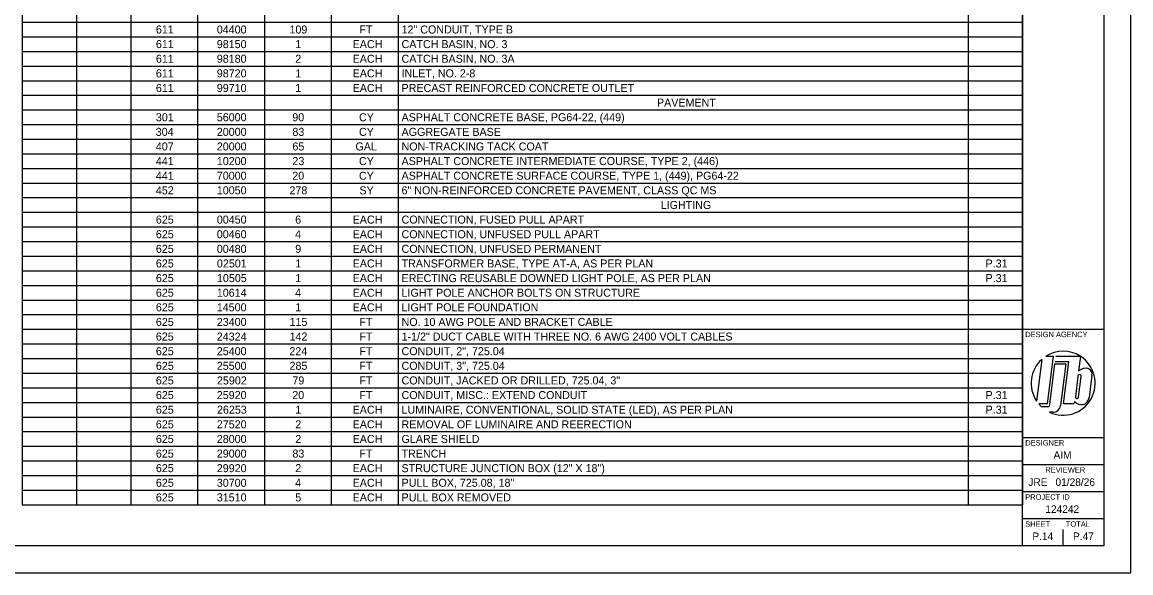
# Model space of a CAD drawing. Extents: x 0 to 34, y 0 to 22.
# Drawn here: x 13.53 to 34, y 0 to 10.16 of the extents above; entities that cross this region are included whole.
import ezdxf

# ---------------------------------------------------------------- set-up
doc = ezdxf.new("R2010")
doc.units = 0
for name, color, linetype in [('Default', 7, 'Continuous'), ('SH_Border', 7, 'Continuous'), ('SH_Cut_Line', 7, 'Continuous'), ('SH_Data', 7, 'Continuous')]:
    doc.layers.add(name, color=color, linetype=linetype)

msp = doc.modelspace()

# ---------------------------------------------------------------- linework, layer by layer
at = {"layer": 'Default'}
for p, q in [((13.53, 10.434), (13.53, 10.164)), ((14.533, 10.434), (14.533, 10.164)), ((15.535, 10.434), (15.535, 10.164)), ((16.769, 10.434), (16.769, 10.164)), ((18.003, 10.434), (18.003, 10.164)), ((19.237, 10.434), (19.237, 10.164)), ((20.471, 10.434), (20.471, 10.164)), ((30.997, 10.434), (30.997, 10.164)), ((32, 10.434), (32, 10.164)), ((13.53, 10.164), (15.535, 10.164)), ((13.53, 10.164), (13.53, 9.354)), ((14.533, 10.164), (14.533, 9.354)), ((15.535, 10.164), (32, 10.164)), ((15.535, 10.164), (15.535, 9.354)), ((16.769, 10.164), (16.769, 9.354)), ((18.003, 10.164), (18.003, 9.354)), ((19.237, 10.164), (19.237, 9.354)), ((20.471, 10.164), (20.471, 9.354)), ((30.997, 10.164), (30.997, 9.354)), ((32, 10.164), (32, 9.354)), ((13.53, 9.894), (15.535, 9.894)), ((15.535, 9.894), (32, 9.894)), ((13.53, 9.624), (15.535, 9.624)), ((15.535, 9.624), (32, 9.624)), ((13.53, 9.354), (15.535, 9.354)), ((13.53, 9.354), (13.53, 8.814)), ((14.533, 9.354), (14.533, 8.814)), ((15.535, 9.354), (32, 9.354)), ((15.535, 9.354), (15.535, 8.814)), ((16.769, 9.354), (16.769, 8.814)), ((18.003, 9.354), (18.003, 8.814)), ((19.237, 9.354), (19.237, 8.814)), ((20.471, 9.354), (20.471, 8.814)), ((30.997, 9.354), (30.997, 8.814)), ((32, 9.354), (32, 8.814)), ((13.53, 9.084), (15.535, 9.084)), ((15.535, 9.084), (32, 9.084)), ((13.53, 8.814), (15.535, 8.814)), ((13.53, 8.814), (13.53, 8.004)), ((14.533, 8.814), (14.533, 8.004)), ((15.535, 8.814), (32, 8.814)), ((15.535, 8.814), (15.535, 8.004)), ((16.769, 8.814), (16.769, 8.004)), ((18.003, 8.814), (18.003, 8.004)), ((19.237, 8.814), (19.237, 8.004)), ((20.471, 8.814), (20.471, 8.004)), ((30.997, 8.814), (30.997, 8.004)), ((32, 8.814), (32, 8.004)), ((13.53, 8.544), (15.535, 8.544)), ((15.535, 8.544), (32, 8.544)), ((13.53, 8.274), (15.535, 8.274)), ((15.535, 8.274), (32, 8.274)), ((13.53, 8.004), (15.535, 8.004)), ((13.53, 8.004), (13.53, 7.465)), ((14.533, 8.004), (14.533, 7.465)), ((15.535, 8.004), (32, 8.004)), ((15.535, 8.004), (15.535, 7.465)), ((16.769, 8.004), (16.769, 7.465)), ((18.003, 8.004), (18.003, 7.465)), ((19.237, 8.004), (19.237, 7.465)), ((20.471, 8.004), (20.471, 7.465)), ((30.997, 8.004), (30.997, 7.465)), ((32, 8.004), (32, 7.465)), ((13.53, 7.735), (15.535, 7.735)), ((15.535, 7.735), (32, 7.735)), ((13.53, 7.465), (15.535, 7.465)), ((13.53, 7.465), (13.53, 6.655)), ((14.533, 7.465), (14.533, 6.655)), ((15.535, 7.465), (32, 7.465)), ((15.535, 7.465), (15.535, 6.655)), ((16.769, 7.465), (16.769, 6.655)), ((18.003, 7.465), (18.003, 6.655)), ((19.237, 7.465), (19.237, 6.655)), ((20.471, 7.465), (20.471, 6.655)), ((30.997, 7.465), (30.997, 6.655)), ((32, 7.465), (32, 6.655)), ((13.53, 7.195), (15.535, 7.195)), ((15.535, 7.195), (32, 7.195)), ((13.53, 6.925), (15.535, 6.925)), ((15.535, 6.925), (32, 6.925)), ((13.53, 6.655), (15.535, 6.655)), ((13.53, 6.655), (13.53, 5.575)), ((14.533, 6.655), (14.533, 5.575)), ((15.535, 6.655), (32, 6.655)), ((15.535, 6.655), (15.535, 5.575)), ((16.769, 6.655), (16.769, 5.575)), ((18.003, 6.655), (18.003, 5.575)), ((19.237, 6.655), (19.237, 5.575)), ((20.471, 6.655), (20.471, 5.575)), ((30.997, 6.655), (30.997, 5.575)), ((32, 6.655), (32, 5.575)), ((13.53, 6.385), (15.535, 6.385)), ((15.535, 6.385), (32, 6.385)), ((13.53, 6.115), (15.535, 6.115)), ((15.535, 6.115), (32, 6.115)), ((13.53, 5.845), (15.535, 5.845)), ((15.535, 5.845), (32, 5.845)), ((13.53, 5.575), (15.535, 5.575)), ((13.53, 5.575), (13.53, 5.305)), ((14.533, 5.575), (14.533, 5.305)), ((15.535, 5.575), (32, 5.575)), ((15.535, 5.575), (15.535, 5.305)), ((16.769, 5.575), (16.769, 5.305)), ((18.003, 5.575), (18.003, 5.305)), ((19.237, 5.575), (19.237, 5.305)), ((20.471, 5.575), (20.471, 5.305)), ((30.997, 5.575), (30.997, 5.305)), ((32, 5.575), (32, 5.305)), ((13.53, 5.305), (15.535, 5.305)), ((13.53, 5.305), (13.53, 4.226)), ((14.533, 5.305), (14.533, 4.226)), ((15.535, 5.305), (32, 5.305)), ((15.535, 5.305), (15.535, 4.226)), ((16.769, 5.305), (16.769, 4.226)), ((18.003, 5.305), (18.003, 4.226)), ((19.237, 5.305), (19.237, 4.226)), ((20.471, 5.305), (20.471, 4.226)), ((30.997, 5.305), (30.997, 4.226)), ((32, 5.305), (32, 4.226)), ((13.53, 5.035), (15.535, 5.035)), ((15.535, 5.035), (32, 5.035)), ((13.53, 4.765), (15.535, 4.765)), ((15.535, 4.765), (32, 4.765)), ((13.53, 4.496), (15.535, 4.496)), ((15.535, 4.496), (32, 4.496)), ((13.53, 4.226), (15.535, 4.226)), ((13.53, 4.226), (13.53, 3.956)), ((14.533, 4.226), (14.533, 3.956)), ((15.535, 4.226), (32, 4.226)), ((15.535, 4.226), (15.535, 3.956)), ((16.769, 4.226), (16.769, 3.956)), ((18.003, 4.226), (18.003, 3.956)), ((19.237, 4.226), (19.237, 3.956)), ((20.471, 4.226), (20.471, 3.956)), ((30.997, 4.226), (30.997, 3.956)), ((32, 4.226), (32, 3.956)), ((13.53, 3.956), (15.535, 3.956)), ((13.53, 3.956), (13.53, 2.876)), ((14.533, 3.956), (14.533, 2.876)), ((15.535, 3.956), (32, 3.956)), ((15.535, 3.956), (15.535, 2.876)), ((16.769, 3.956), (16.769, 2.876)), ((18.003, 3.956), (18.003, 2.876)), ((19.237, 3.956), (19.237, 2.876)), ((20.471, 3.956), (20.471, 2.876)), ((30.997, 3.956), (30.997, 2.876)), ((32, 3.956), (32, 2.876)), ((13.53, 3.686), (15.535, 3.686)), ((15.535, 3.686), (32, 3.686)), ((13.53, 3.416), (15.535, 3.416)), ((15.535, 3.416), (32, 3.416)), ((13.53, 3.146), (15.535, 3.146)), ((15.535, 3.146), (32, 3.146)), ((13.53, 2.876), (15.535, 2.876)), ((13.53, 2.876), (13.53, 2.606)), ((14.533, 2.876), (14.533, 2.606)), ((15.535, 2.876), (32, 2.876)), ((15.535, 2.876), (15.535, 2.606)), ((16.769, 2.876), (16.769, 2.606)), ((18.003, 2.876), (18.003, 2.606)), ((19.237, 2.876), (19.237, 2.606)), ((20.471, 2.876), (20.471, 2.606)), ((30.997, 2.876), (30.997, 2.606)), ((32, 2.876), (32, 2.606)), ((13.53, 2.606), (15.535, 2.606)), ((13.53, 2.606), (13.53, 1.527)), ((14.533, 2.606), (14.533, 1.527)), ((15.535, 2.606), (32, 2.606)), ((15.535, 2.606), (15.535, 1.527)), ((16.769, 2.606), (16.769, 1.527)), ((18.003, 2.606), (18.003, 1.527)), ((19.237, 2.606), (19.237, 1.527)), ((20.471, 2.606), (20.471, 1.527)), ((30.997, 2.606), (30.997, 1.527)), ((32, 2.606), (32, 1.527)), ((13.53, 2.336), (15.535, 2.336)), ((15.535, 2.336), (32, 2.336)), ((13.53, 2.066), (15.535, 2.066)), ((15.535, 2.066), (32, 2.066)), ((13.53, 1.796), (15.535, 1.796)), ((15.535, 1.796), (32, 1.796)), ((13.53, 1.527), (15.535, 1.527)), ((13.53, 1.527), (13.53, 1.257)), ((14.533, 1.527), (14.533, 1.257)), ((15.535, 1.527), (32, 1.527)), ((15.535, 1.527), (15.535, 1.257)), ((16.769, 1.527), (16.769, 1.257)), ((18.003, 1.527), (18.003, 1.257)), ((19.237, 1.527), (19.237, 1.257)), ((20.471, 1.527), (20.471, 1.257)), ((30.997, 1.527), (30.997, 1.257)), ((32, 1.527), (32, 1.257)), ((13.53, 1.257), (15.535, 1.257)), ((15.535, 1.257), (32, 1.257))]:
    msp.add_line(p, q, dxfattribs=at)
at = {"layer": 'SH_Border'}
for p, q in [((32, 0.5), (32, 21.5)), ((32, 4.5), (33.5, 4.5)), ((32, 2.5), (33.5, 2.5)), ((32, 2), (33.5, 2)), ((32, 1.5), (33.5, 1.5)), ((32, 1), (33.5, 1))]:
    msp.add_line(p, q, dxfattribs=at)
msp.add_lwpolyline([(1.5, 21.5), (33.5, 21.5), (33.5, 0.5), (1.5, 0.5)], close=True, dxfattribs=at)
at = {"layer": 'SH_Cut_Line'}
msp.add_lwpolyline([(0, 0), (34, 0), (34, 22), (0, 22)], close=True, dxfattribs=at)
at = {"layer": 'SH_Data'}
for p, q in [((32.356, 3.94), (32.259, 3.171)), ((32.432, 3.998), (32.567, 3.998)), ((32.567, 3.998), (32.456, 3.118)), ((32.856, 3.896), (32.604, 3.896)), ((32.617, 4), (33.065, 4)), ((32.758, 3.118), (32.856, 3.896)), ((33.07, 3.996), (33.035, 3.72)), ((32.504, 3.104), (32.599, 3.855)), ((32.599, 3.855), (32.801, 3.855)), ((32.801, 3.855), (32.704, 3.089)), ((32.75, 3.5), (32.75, 3.5)), ((33.024, 3.631), (32.976, 3.25)), ((33.036, 3.243), (33.084, 3.624)), ((33.283, 3.648), (33.231, 3.237)), ((32.456, 3.118), (32.299, 3.118)), ((32.947, 3.118), (32.758, 3.118)), ((32.964, 3.161), (32.947, 3.118)), ((32.347, 3.068), (32.462, 3.068)), ((32.564, 2.966), (32.498, 2.966)), ((32.375, 0.675), (32.375, 0.675)), ((32.75, 0.5), (32.75, 0.8))]:
    msp.add_line(p, q, dxfattribs=at)
for centre, radius, start, end in [((32.75, 3.5), 0.591, 131.8253, 213.7822), ((32.75, 3.5), 0.591, 57.726, 122.5688), ((32.75, 3.5), 0.591, 244.7646, 57.1575), ((33.17, 3.586), 0.19, 105.9444, 135.0487), ((33.164, 3.6), 0.175, 66.6782, 105.4185), ((33.177, 3.669), 0.108, 349.2072, 58.7163), ((33.054, 3.628), 0.0301, 352.3298, 173.2777), ((32.75, 3.5), 0.591, 220.2786, 227.0158), ((32.462, 3.109), 0.0417, 270, 352.8038), ((32.564, 3.106), 0.141, 270, 352.8038), ((33.081, 3.255), 0.151, 218.6264, 353.0883), ((33.006, 3.246), 0.0301, 172.3335, 353.274)]:
    msp.add_arc(centre, radius, start, end, dxfattribs=at)

# ---------------------------------------------------------------- texts
at = {"layer": 'Default'}
for s, height, p in [('611', 0.1478, (15.999, 9.955)), ('04400', 0.1478, (17.124, 9.955)), ('109', 0.1478, (18.466, 9.955)), ('FT', 0.1478, (19.756, 9.955)), ('12" CONDUIT, TYPE B', 0.14781, (20.535, 9.955)), ('611', 0.1478, (15.999, 9.685)), ('98150', 0.1478, (17.124, 9.685)), ('1', 0.148, (18.573, 9.685)), ('EACH', 0.1478, (19.632, 9.685)), ('CATCH BASIN, NO. 3', 0.14781, (20.535, 9.685)), ('611', 0.1478, (15.999, 9.415)), ('98180', 0.1478, (17.124, 9.415)), ('2', 0.148, (18.573, 9.415)), ('EACH', 0.1478, (19.632, 9.415)), ('CATCH BASIN, NO. 3A', 0.14781, (20.535, 9.415)), ('611', 0.1478, (15.999, 9.145)), ('98720', 0.1478, (17.124, 9.145)), ('1', 0.148, (18.573, 9.145)), ('EACH', 0.1478, (19.632, 9.145)), ('INLET, NO. 2-8', 0.14781, (20.535, 9.145)), ('611', 0.1478, (15.999, 8.875)), ('99710', 0.1478, (17.124, 8.875)), ('1', 0.148, (18.573, 8.875)), ('EACH', 0.1478, (19.632, 8.875)), ('PRECAST REINFORCED CONCRETE OUTLET', 0.14781, (20.535, 8.875)), ('PAVEMENT', 0.1478, (25.251, 8.605)), ('301', 0.1478, (15.999, 8.335)), ('56000', 0.1478, (17.124, 8.335)), ('90', 0.1478, (18.518, 8.335)), ('CY', 0.1478, (19.749, 8.335)), ('ASPHALT CONCRETE BASE, PG64-22, (449)', 0.14781, (20.535, 8.335)), ('304', 0.1478, (15.996, 8.065)), ('20000', 0.1478, (17.124, 8.065)), ('83', 0.1478, (18.52, 8.065)), ('CY', 0.1478, (19.749, 8.065)), ('AGGREGATE BASE', 0.14781, (20.535, 8.065)), ('407', 0.1478, (15.998, 7.796)), ('20000', 0.1478, (17.124, 7.796)), ('65', 0.1478, (18.52, 7.796)), ('GAL', 0.1478, (19.684, 7.796)), ('NON-TRACKING TACK COAT', 0.14781, (20.535, 7.796)), ('441', 0.1478, (15.999, 7.526)), ('10200', 0.1478, (17.124, 7.526)), ('23', 0.1478, (18.52, 7.526)), ('CY', 0.1478, (19.749, 7.526)), ('ASPHALT CONCRETE INTERMEDIATE COURSE, TYPE 2, (446)', 0.14781, (20.535, 7.526)), ('441', 0.1478, (15.999, 7.256)), ('70000', 0.1478, (17.124, 7.256)), ('20', 0.1478, (18.518, 7.256)), ('CY', 0.1478, (19.749, 7.256)), ('ASPHALT CONCRETE SURFACE COURSE, TYPE 1, (449), PG64-22', 0.14781, (20.535, 7.256)), ('452', 0.1478, (15.999, 6.986)), ('10050', 0.1478, (17.124, 6.986)), ('278', 0.1478, (18.465, 6.986)), ('SY', 0.1478, (19.757, 6.986)), ('6" NON-REINFORCED CONCRETE PAVEMENT, CLASS QC MS', 0.14781, (20.535, 6.986)), ('LIGHTING', 0.1478, (25.32, 6.716)), ('625', 0.1478, (15.999, 6.446)), ('00450', 0.1478, (17.124, 6.446)), ('6', 0.148, (18.571, 6.446)), ('EACH', 0.1478, (19.632, 6.446)), ('CONNECTION, FUSED PULL APART', 0.14781, (20.535, 6.446)), ('625', 0.1478, (15.999, 6.176)), ('00460', 0.1478, (17.124, 6.176)), ('4', 0.148, (18.57, 6.176)), ('EACH', 0.1478, (19.632, 6.176)), ('CONNECTION, UNFUSED PULL APART', 0.14781, (20.535, 6.176)), ('625', 0.1478, (15.999, 5.906)), ('00480', 0.1478, (17.124, 5.906)), ('9', 0.148, (18.572, 5.906)), ('EACH', 0.1478, (19.632, 5.906)), ('CONNECTION, UNFUSED PERMANENT', 0.14781, (20.535, 5.906)), ('625', 0.1478, (15.999, 5.636)), ('02501', 0.1478, (17.126, 5.636)), ('1', 0.148, (18.573, 5.636)), ('EACH', 0.1478, (19.632, 5.636)), ('TRANSFORMER BASE, TYPE AT-A, AS PER PLAN', 0.14781, (20.535, 5.636)), ('P.31', 0.1478, (31.318, 5.636)), ('625', 0.1478, (15.999, 5.366)), ('10505', 0.1478, (17.127, 5.366)), ('1', 0.148, (18.573, 5.366)), ('EACH', 0.1478, (19.632, 5.366)), ('ERECTING REUSABLE DOWNED LIGHT POLE, AS PER PLAN', 0.14781, (20.535, 5.366)), ('P.31', 0.1478, (31.318, 5.366)), ('625', 0.1478, (15.999, 5.096)), ('10614', 0.1478, (17.124, 5.096)), ('4', 0.148, (18.57, 5.096)), ('EACH', 0.1478, (19.632, 5.096)), ('LIGHT POLE ANCHOR BOLTS ON STRUCTURE', 0.14781, (20.535, 5.096)), ('625', 0.1478, (15.999, 4.827)), ('14500', 0.1478, (17.124, 4.827)), ('1', 0.148, (18.573, 4.827)), ('EACH', 0.1478, (19.632, 4.827)), ('LIGHT POLE FOUNDATION', 0.14781, (20.535, 4.827)), ('625', 0.1478, (15.999, 4.557)), ('23400', 0.1478, (17.124, 4.557)), ('115', 0.1478, (18.467, 4.557)), ('FT', 0.1478, (19.756, 4.557)), ('NO. 10 AWG POLE AND BRACKET CABLE', 0.14781, (20.535, 4.557)), ('625', 0.1478, (15.999, 4.287)), ('24324', 0.1478, (17.124, 4.287)), ('142', 0.1478, (18.467, 4.287)), ('FT', 0.1478, (19.756, 4.287)), ('1-1/2" DUCT CABLE WITH THREE NO. 6 AWG 2400 VOLT CABLES', 0.14781, (20.535, 4.287)), ('625', 0.1478, (15.999, 4.017)), ('25400', 0.1478, (17.124, 4.017)), ('224', 0.1478, (18.464, 4.017)), ('FT', 0.1478, (19.756, 4.017)), ('CONDUIT, 2", 725.04', 0.14781, (20.535, 4.017)), ('625', 0.1478, (15.999, 3.747)), ('25500', 0.1478, (17.124, 3.747)), ('285', 0.1478, (18.467, 3.747)), ('FT', 0.1478, (19.756, 3.747)), ('CONDUIT, 3", 725.04', 0.14781, (20.535, 3.747)), ('625', 0.1478, (15.999, 3.477)), ('25902', 0.1478, (17.127, 3.477)), ('79', 0.1478, (18.519, 3.477)), ('FT', 0.1478, (19.756, 3.477)), ('CONDUIT, JACKED OR DRILLED, 725.04, 3"', 0.14781, (20.535, 3.477)), ('625', 0.1478, (15.999, 3.207)), ('25920', 0.1478, (17.124, 3.207)), ('20', 0.1478, (18.518, 3.207)), ('FT', 0.1478, (19.756, 3.207)), ('CONDUIT, MISC.: EXTEND CONDUIT', 0.14781, (20.535, 3.207)), ('P.31', 0.1478, (31.318, 3.207)), ('625', 0.1478, (15.999, 2.937)), ('26253', 0.1478, (17.127, 2.937)), ('1', 0.148, (18.573, 2.937)), ('EACH', 0.1478, (19.632, 2.937)), ('LUMINAIRE, CONVENTIONAL, SOLID STATE (LED), AS PER PLAN', 0.14781, (20.535, 2.937)), ('P.31', 0.1478, (31.318, 2.937)), ('625', 0.1478, (15.999, 2.667)), ('27520', 0.1478, (17.124, 2.667)), ('2', 0.148, (18.573, 2.667)), ('EACH', 0.1478, (19.632, 2.667)), ('REMOVAL OF LUMINAIRE AND REERECTION', 0.14781, (20.535, 2.667)), ('625', 0.1478, (15.999, 2.397)), ('28000', 0.1478, (17.124, 2.397)), ('2', 0.148, (18.573, 2.397)), ('EACH', 0.1478, (19.632, 2.397)), ('GLARE SHIELD', 0.14781, (20.535, 2.397)), ('625', 0.1478, (15.999, 2.127)), ('29000', 0.1478, (17.124, 2.127)), ('83', 0.1478, (18.52, 2.127)), ('FT', 0.1478, (19.756, 2.127)), ('TRENCH', 0.1478, (20.535, 2.127)), ('625', 0.1478, (15.999, 1.858)), ('29920', 0.1478, (17.124, 1.858)), ('2', 0.148, (18.573, 1.858)), ('EACH', 0.1478, (19.632, 1.858)), ('STRUCTURE JUNCTION BOX (12" X 18")', 0.14781, (20.535, 1.858)), ('625', 0.1478, (15.999, 1.588)), ('30700', 0.1478, (17.124, 1.588)), ('4', 0.148, (18.57, 1.588)), ('EACH', 0.1478, (19.632, 1.588)), ('PULL BOX, 725.08, 18"', 0.14781, (20.535, 1.588)), ('625', 0.1478, (15.999, 1.318)), ('31510', 0.1478, (17.124, 1.318)), ('5', 0.148, (18.573, 1.318)), ('EACH', 0.1478, (19.632, 1.318)), ('PULL BOX REMOVED', 0.14781, (20.535, 1.318))]:
    msp.add_text(s, height=height, dxfattribs=at).set_placement(p)
at = {"layer": 'SH_Data'}
for s, height, p in [('DESIGN AGENCY', 0.1, (32.05, 4.35)), ('DESIGNER', 0.1, (32.05, 2.35)), ('AIM', 0.14, (32.573, 2.105)), ('REVIEWER', 0.1, (32.422, 1.85)), ('JRE', 0.14, (32.107, 1.605)), ('01/28/26', 0.14, (32.609, 1.605)), ('PROJECT ID', 0.1, (32.05, 1.35)), ('124242', 0.14, (32.421, 1.105)), ('SHEET', 0.1, (32.05, 0.85)), ('TOTAL', 0.1, (32.8, 0.85)), ('P.14', 0.14, (32.182, 0.605)), ('P.47', 0.14, (32.933, 0.605))]:
    msp.add_text(s, height=height, dxfattribs=at).set_placement(p)

doc.saveas('drawing.dxf')
